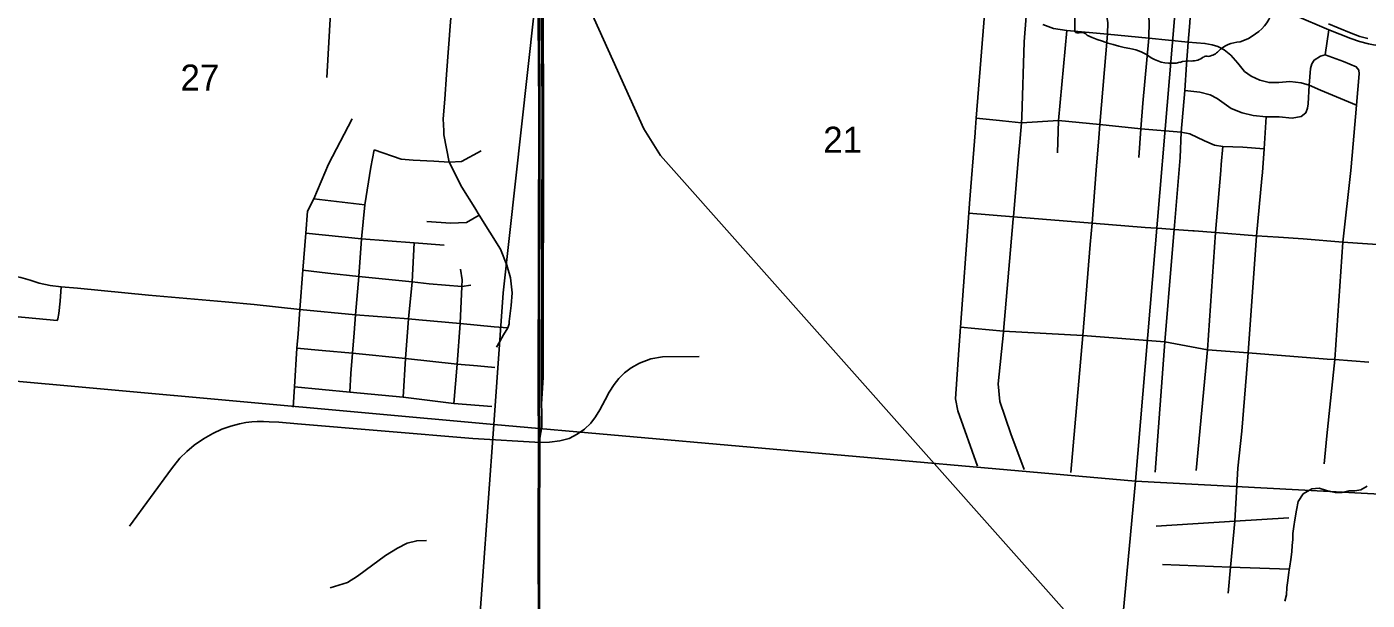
# Model space of a CAD drawing. Extents: x 0 to 34, y 0 to 22.
# Drawn here: x 5.747 to 7.896, y 15.439 to 16.358 of the extents above; entities that cross this region are included whole.
import ezdxf

# ---------------------------------------------------------------- set-up
doc = ezdxf.new("R2010")
doc.units = 0
for name, color, linetype in [('GM_X_City_Street', 7, 'Continuous'), ('GM_X_Corporation', 7, 'Continuous'), ('GM_X_County_Road', 7, 'Continuous'), ('GM_X_Minor_River', 7, 'Continuous'), ('GM_X_Rail_Line', 7, 'Continuous'), ('GM_X_Section_Text', 7, 'Continuous'), ('GM_X_State_Route', 7, 'Continuous'), ('GM_X_State_Shield', 7, 'Continuous')]:
    doc.layers.add(name, color=color, linetype=linetype)

msp = doc.modelspace()

# ---------------------------------------------------------------- linework, layer by layer
at = {"layer": 'GM_X_City_Street'}
for p, q in [((7.2689, 16.2115), (7.3062, 16.2078)), ((7.6616, 16.1376), (7.6641, 16.1665)), ((6.2067, 16.0822), (6.2885, 16.0729))]:
    msp.add_line(p, q, dxfattribs=at)
for points in [[(7.5958, 16.1486), (7.5973, 16.189), (7.6031, 16.2558), (7.606, 16.2979), (7.6085, 16.3338), (7.6105, 16.3582), (7.6131, 16.3871), (7.6175, 16.4441), (7.6188, 16.4522), (7.621, 16.4779), (7.6228, 16.4986), (7.6242, 16.5095), (7.6304, 16.5939), (7.6359, 16.653), (7.6444, 16.748), (7.6534, 16.8441), (7.6677, 16.9662), (7.675, 17.0675)], [(6.2278, 16.2771), (6.2352, 16.4091), (6.2363, 16.4219), (6.2444, 16.5069), (6.2509, 16.582), (6.2511, 16.5949), (6.2582, 16.6785), (6.2653, 16.7489)], [(7.338, 16.1671), (7.3412, 16.2044), (7.3419, 16.2133), (7.3454, 16.3343), (7.3488, 16.3754), (7.3526, 16.393), (7.3619, 16.4107), (7.3778, 16.4395), (7.3833, 16.4584), (7.3855, 16.4746), (7.3871, 16.4896)], [(7.4652, 16.18), (7.467, 16.2014), (7.4795, 16.3462), (7.4797, 16.3653), (7.477, 16.3807), (7.4732, 16.3925), (7.4634, 16.4185), (7.4615, 16.4253), (7.4602, 16.4326), (7.4642, 16.4802), (7.4649, 16.4895)], [(7.5295, 16.1485), (7.5329, 16.1947), (7.5359, 16.2355), (7.5453, 16.3398), (7.5458, 16.367), (7.5431, 16.3968), (7.5439, 16.4111)], [(7.3754, 16.3619), (7.3928, 16.3553), (7.4143, 16.3525), (7.4795, 16.3462), (7.5453, 16.3398), (7.6085, 16.3338), (7.6353, 16.3315), (7.6472, 16.3292), (7.6562, 16.3264), (7.6665, 16.3213), (7.6769, 16.3127), (7.6881, 16.3001), (7.6987, 16.2867), (7.7094, 16.2789), (7.7236, 16.2724), (7.7382, 16.2688), (7.7538, 16.269), (7.7717, 16.2704), (7.7898, 16.2684), (7.8027, 16.2646), (7.8206, 16.2565), (7.8784, 16.2326)], [(7.7896, 16.2144), (7.797, 16.2204), (7.7999, 16.2275), (7.801, 16.2348), (7.8027, 16.2646), (7.8046, 16.2912), (7.8069, 16.2987), (7.8107, 16.3048), (7.8206, 16.3111), (7.8284, 16.3132), (7.8339, 16.3536)], [(7.3992, 16.156), (7.4008, 16.2078), (7.4143, 16.3525)], [(7.8284, 16.3132), (7.8576, 16.3023), (7.878, 16.2938), (7.882, 16.2886), (7.8827, 16.2829)], [(7.8715, 16.1519), (7.8784, 16.2326), (7.8827, 16.2829)], [(7.6031, 16.2558), (7.6274, 16.2533), (7.644, 16.2493), (7.6549, 16.2434), (7.6777, 16.227), (7.695, 16.2201), (7.7126, 16.2161), (7.7336, 16.2139), (7.7545, 16.2137), (7.7755, 16.2119), (7.7896, 16.2144)], [(6.174, 15.7481), (6.1759, 15.7806), (6.1797, 15.8428), (6.1816, 15.8661), (6.1845, 15.9048), (6.1891, 15.9678), (6.1943, 16.0271), (6.197, 16.0623), (6.2067, 16.0822), (6.2303, 16.1381), (6.2682, 16.2108)], [(7.3062, 16.2078), (7.3109, 16.2074), (7.3412, 16.2044), (7.4008, 16.2078), (7.467, 16.2014), (7.5329, 16.1947), (7.5973, 16.189), (7.6114, 16.1864), (7.6347, 16.1753), (7.6508, 16.1686), (7.6641, 16.1665), (7.6961, 16.165), (7.7303, 16.1624)], [(7.7275, 16.1248), (7.7303, 16.1624), (7.7336, 16.2139)], [(6.2644, 15.7723), (6.2661, 15.8024), (6.2691, 15.8348), (6.2713, 15.8673), (6.2738, 15.8961), (6.2788, 15.9579), (6.2831, 16.0184), (6.2885, 16.0729), (6.2985, 16.1333), (6.3035, 16.1611)], [(6.3035, 16.1611), (6.3471, 16.146), (6.3662, 16.1443), (6.3993, 16.1425), (6.4241, 16.141)], [(6.4241, 16.141), (6.4435, 16.1421), (6.4752, 16.1595)], [(7.3457, 15.6485), (7.3245, 15.7057), (7.3068, 15.7574), (7.3042, 15.7856), (7.3124, 15.8685), (7.3125, 15.87), (7.3282, 16.05), (7.3284, 16.0535), (7.3372, 16.1573), (7.338, 16.1671)], [(7.4207, 15.6433), (7.4395, 15.8634), (7.4517, 16.0093), (7.4545, 16.0432), (7.461, 16.1283), (7.4652, 16.18)], [(7.5559, 15.6439), (7.5713, 15.8528), (7.5824, 15.9888), (7.5862, 16.0333), (7.5958, 16.1486)], [(7.8268, 15.6572), (7.831, 15.7024), (7.8435, 15.8245), (7.8564, 16.0128), (7.8694, 16.1277), (7.8715, 16.1519)], [(7.6214, 15.6469), (7.6394, 15.8403), (7.6522, 16.0284), (7.6608, 16.1279), (7.6616, 16.1376)], [(7.6726, 15.4502), (7.6765, 15.4919), (7.6833, 15.5653), (7.6882, 15.6503), (7.6947, 15.7098), (7.7046, 15.8353), (7.7183, 16.0232), (7.7267, 16.1149), (7.7275, 16.1248)], [(6.388, 16.0462), (6.426, 16.0435), (6.4514, 16.0445), (6.4721, 16.0559)], [(7.2571, 16.0593), (7.3284, 16.0535), (7.4545, 16.0432), (7.5395, 16.0365), (7.5663, 16.0347)], [(7.5663, 16.0347), (7.5862, 16.0333), (7.6162, 16.0311)], [(7.6162, 16.0311), (7.6182, 16.0309), (7.6522, 16.0284), (7.7183, 16.0232), (7.7534, 16.0208), (7.7927, 16.018), (7.8564, 16.0128), (7.9277, 16.0081), (7.9566, 16.0029)], [(6.1943, 16.0271), (6.2831, 16.0184), (6.368, 16.0116), (6.4157, 16.008)], [(6.35, 15.7641), (6.3541, 15.8265), (6.3586, 15.8898), (6.3646, 15.9494), (6.368, 16.0116)], [(6.1891, 15.9678), (6.2295, 15.9633), (6.2788, 15.9579), (6.3646, 15.9494), (6.3917, 15.9459), (6.4443, 15.9419), (6.4584, 15.9441)], [(6.4314, 15.7541), (6.4366, 15.817), (6.4414, 15.8823), (6.4443, 15.9419), (6.4449, 15.9522), (6.4418, 15.9697)], [(5.7952, 15.887), (5.7967, 15.8899), (5.798, 15.8983), (5.8003, 15.9182), (5.802, 15.9412)], [(5.6313, 15.904), (5.647, 15.9012), (5.7952, 15.887)], [(7.2436, 15.8765), (7.3125, 15.87), (7.4395, 15.8634), (7.5713, 15.8528), (7.6394, 15.8403), (7.7046, 15.8353), (7.8316, 15.8254), (7.8435, 15.8245), (7.8982, 15.8203)], [(6.1797, 15.8428), (6.2205, 15.8393), (6.2691, 15.8348), (6.3541, 15.8265), (6.4366, 15.817), (6.4695, 15.8145), (6.4971, 15.8118)], [(6.1759, 15.7806), (6.2644, 15.7723), (6.35, 15.7641), (6.4314, 15.7541), (6.4922, 15.7493)], [(7.5573, 15.5574), (7.6833, 15.5653), (7.7698, 15.5707)], [(7.5673, 15.496), (7.6765, 15.4919), (7.7703, 15.4884)]]:
    msp.add_lwpolyline(points, dxfattribs=at)
at = {"layer": 'GM_X_Corporation'}
for points in [[(5.5455, 16.8552), (6.5907, 16.7563), (6.5598, 16.3771), (6.5104, 15.9318), (6.4956, 15.7207), (5.4696, 15.8133)], [(6.5907, 16.7563), (7.6101, 16.6513), (7.5243, 15.6293), (6.4956, 15.7207), (6.5104, 15.9318), (6.5598, 16.3771)], [(7.6101, 16.6513), (8.6706, 16.571), (8.5797, 15.5737), (7.5243, 15.6293)], [(5.4696, 15.8133), (6.4956, 15.7207), (6.423, 14.72), (5.3881, 14.7897)], [(6.4956, 15.7207), (7.5243, 15.6293), (7.4312, 14.6313), (6.423, 14.72)], [(7.5243, 15.6293), (8.5797, 15.5737), (8.4854, 14.5806), (8.0353, 14.6105), (7.5723, 14.6206), (7.4312, 14.6313)]]:
    msp.add_lwpolyline(points, close=True, dxfattribs=at)
at = {"layer": 'GM_X_County_Road'}
for points in [[(7.2672, 16.189), (7.2689, 16.2115), (7.2846, 16.4116), (7.2915, 16.4987)], [(6.4151, 16.1913), (6.4145, 16.2107), (6.4169, 16.2424), (6.4198, 16.2819), (6.4258, 16.3663), (6.4277, 16.3849), (6.4306, 16.4021), (6.4367, 16.4206), (6.4371, 16.4215)], [(6.5203, 15.8856), (6.5232, 15.9111), (6.5248, 15.9314), (6.5221, 15.9554), (6.5164, 15.9761), (6.5062, 16.0016), (6.4721, 16.0559), (6.4651, 16.0677), (6.4441, 16.101), (6.4241, 16.141), (6.4153, 16.1852), (6.4151, 16.1913)], [(7.2706, 15.6537), (7.2393, 15.7423), (7.2358, 15.7618), (7.2409, 15.8402), (7.2436, 15.8765), (7.2571, 16.0593), (7.2582, 16.0751), (7.2671, 16.1881), (7.2672, 16.189)], [(5.632, 15.9677), (5.6449, 15.9664), (5.6862, 15.9633), (5.7212, 15.9592), (5.7372, 15.9561), (5.7521, 15.9519), (5.7668, 15.9473), (5.7841, 15.9435), (5.802, 15.9412), (5.8282, 15.9389), (5.9421, 15.9278), (6.0649, 15.9174), (6.1114, 15.9127), (6.1845, 15.9048), (6.2738, 15.8961), (6.3586, 15.8898), (6.3752, 15.8883), (6.4414, 15.8823), (6.496, 15.8771), (6.518, 15.8755)], [(6.4998, 15.8444), (6.5053, 15.8536), (6.5111, 15.864), (6.518, 15.8755), (6.5199, 15.8817), (6.5203, 15.8856)]]:
    msp.add_lwpolyline(points, dxfattribs=at)
at = {"layer": 'GM_X_Minor_River'}
msp.add_lwpolyline([(7.8958, 15.6218), (7.8853, 15.6156), (7.8758, 15.6143), (7.8663, 15.6138), (7.8552, 15.6115), (7.8445, 15.6114), (7.8306, 15.6145), (7.8185, 15.6182), (7.8067, 15.6174), (7.7931, 15.6094), (7.7848, 15.5971), (7.7821, 15.5831), (7.7794, 15.5676), (7.7779, 15.557), (7.7765, 15.5456), (7.7766, 15.5361), (7.7752, 15.5266), (7.7749, 15.516), (7.773, 15.5042), (7.7715, 15.4932), (7.7701, 15.4834), (7.7686, 15.4705), (7.7667, 15.4588), (7.766, 15.4474), (7.7638, 15.4372)], dxfattribs=at)
at = {"layer": 'GM_X_Rail_Line'}
for points in [[(6.5712, 16.557), (6.5762, 16.5461), (6.6563, 16.3712), (6.7362, 16.1947), (6.7626, 16.1517), (8.1595, 14.579)], [(6.569, 15.6986), (6.5723, 15.7166), (6.5721, 15.7765), (6.5727, 16.226), (6.572, 16.3727), (6.5718, 16.5235), (6.5684, 16.5456)], [(6.5721, 15.7533), (6.5745, 15.7963), (6.5751, 16.226), (6.5744, 16.3728), (6.5742, 16.5096), (6.5718, 16.5235)], [(6.5674, 15.2173), (6.5667, 15.5464), (6.5671, 15.6917), (6.5668, 15.7765), (6.5674, 16.226), (6.5667, 16.3727)], [(6.5693, 15.2173), (6.5686, 15.5464), (6.569, 15.6917), (6.5687, 15.7765), (6.5694, 16.226), (6.5686, 16.3727)], [(5.9115, 15.5573), (5.9786, 15.6496), (5.9822, 15.6541), (5.992, 15.6663), (6.0033, 15.6774), (6.0149, 15.6873), (6.03, 15.6976), (6.0448, 15.7061), (6.0592, 15.713), (6.0738, 15.718), (6.0878, 15.7213), (6.098, 15.7235), (6.1077, 15.7248), (6.1159, 15.7254), (6.126, 15.7251), (6.1351, 15.7248), (6.1508, 15.724), (6.1805, 15.7217), (6.4618, 15.6978), (6.5702, 15.6915), (6.5849, 15.6919), (6.6015, 15.6945), (6.616, 15.6982), (6.6293, 15.7049), (6.6407, 15.7131), (6.6508, 15.7227), (6.6587, 15.7326), (6.6653, 15.7442), (6.6739, 15.7601), (6.6804, 15.7724), (6.6882, 15.7847), (6.696, 15.7943), (6.7048, 15.8033), (6.7154, 15.8111), (6.7292, 15.8189), (6.7473, 15.8257), (6.7659, 15.8292), (6.8244, 15.8295)], [(6.2329, 15.4586), (6.2608, 15.4673), (6.277, 15.4774), (6.2892, 15.4865), (6.3218, 15.5103), (6.3412, 15.522), (6.3564, 15.53), (6.3718, 15.5341), (6.3876, 15.5345)]]:
    msp.add_lwpolyline(points, dxfattribs=at)
at = {"layer": 'GM_X_State_Route'}
for points in [[(7.3871, 16.4896), (7.4067, 16.4863), (7.4339, 16.4834), (7.4642, 16.4802), (7.4946, 16.4771), (7.5171, 16.4747), (7.5306, 16.4732), (7.5423, 16.4708), (7.5547, 16.4678), (7.5691, 16.4634), (7.5923, 16.4545), (7.6175, 16.4441), (7.6398, 16.4347), (7.6813, 16.4174), (7.7301, 16.3971), (7.7788, 16.3767), (7.8339, 16.3536), (7.8692, 16.3392), (7.8835, 16.3344), (7.8978, 16.3307), (7.9057, 16.3291), (7.9131, 16.3281), (7.9268, 16.3264), (7.9531, 16.3239)], [(7.8335, 16.3628), (7.8493, 16.3563), (7.8697, 16.3478), (7.8839, 16.3427), (7.8967, 16.3394)]]:
    msp.add_lwpolyline(points, dxfattribs=at)
at = {"layer": 'GM_X_State_Shield'}
msp.add_line((7.4268, 16.5523), (7.4268, 16.3522), dxfattribs=at)
for centre, major_axis, start_param, end_param in [((7.6586, 16.3989), (0.0874, 0), 5.101752, 6.440018), ((7.4306, 16.3518), (0.00385, 0), 3.00124, 4.508301), ((7.4312, 16.3722), (0.0294, 0), 4.665946, 4.897461), ((7.4372, 16.3406), (0.0106, 0), 0.519207, 1.627899), ((7.571, 16.5204), (0.2524, 0), 4.195997, 4.488961), ((7.6954, 16.296), (0.0479, 0), 1.647645, 2.488434), ((7.4958, 16.2623), (0.079, 0), 0.823519, 1.323587), ((7.6138, 16.3247), (0.0267, 0), 4.691044, 5.507374), ((7.638, 16.3053), (0.00752, 0), 1.147584, 2.315152), ((7.6348, 16.3328), (0.0282, 0), 4.937069, 5.64225), ((7.5812, 16.3397), (0.0501, 0), 4.026481, 4.996735), ((7.6102, 16.2705), (0.0412, 0), 1.495662, 1.94098)]:
    msp.add_ellipse(centre, major_axis=major_axis, ratio=0.8, start_param=start_param, end_param=end_param, dxfattribs=at)

# ---------------------------------------------------------------- texts
at = {"layer": 'GM_X_Section_Text'}
for s, p in [('27', (5.9931, 16.2558)), ('21', (7.0235, 16.1561))]:
    msp.add_text(s, height=0.04186, rotation=0, dxfattribs=at).set_placement(p)

doc.saveas('drawing.dxf')
